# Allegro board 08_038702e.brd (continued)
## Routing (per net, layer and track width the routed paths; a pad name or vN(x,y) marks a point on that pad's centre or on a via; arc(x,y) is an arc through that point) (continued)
IO_L12_MRCC_12_JX3_P: length 74.2
  TOP w0.089: U1.AC13 v1(24.22,31.59)
  L7_SIG w0.089: v1(14.02,45.07) 12.63,45.07 12.24,45.45 12.24,46.06 12.9,46.72 13.89,46.72 14.35,46.26 14.84,46.26 15.4,45.7 16.18,45.7 16.56,46.08 16.56,51.16 16.18,51.54 12.37,51.54 11.99,51.92 11.99,53.83 11.61,54.21 10.85,54.21 10.47,54.59 10.47,57.47 11,58 16.42,58 16.44,58.02 19.97,58.02 20.5,57.49 20.5,55.99 20.88,55.61 24.94,55.61 25.33,55.23 25.33,50.78 24.94,50.4 20.88,50.4 20.5,50.02 20.5,46.46 20.88,46.08 22.26,46.08 23.84,44.5 23.84,31.96 v1(24.22,31.59)
  BOTTOM w0.089: JX3.86 13.29,44.97 13.64,45.32 13.77,45.32 v1(14.02,45.07)
IO_L12_MRCC_13_JX2_N: length 72.1
  TOP w0.089: U1.AC24 v1(24.22,19.59)
  L4_SIG w0.089: v1(45.52,8.49) 45.52,6.68 44.41,5.57 37.26,5.57 36.88,5.95 36.88,6.59 37.26,6.97 40.59,6.97 40.97,7.35 40.97,8.11 40.59,8.49 39.47,8.49 39.39,8.41 38.9,8.41 38.82,8.49 38.68,8.49 38.05,9.13 37.64,9.13 35.36,11.41 32.06,11.41 31.8,11.67 31.8,14.06 32.95,15.2 32.95,16.98 32.58,17.34 32.58,25.81 32.39,26 32.07,26 31.88,25.81 31.88,14.84 31.5,14.46 31.29,14.46 30.91,14.08 30.91,13.57 30.49,13.14 30.22,13.14 30.13,13.06 27.63,13.06 27.23,13.47 27.23,14.86 27.12,14.97 25.95,14.97 25.55,15.37 25.55,19.73 25.32,19.96 24.59,19.96 v1(24.22,19.59)
  BOTTOM w0.089: v1(45.52,8.49) 45.26,8.24 45.26,7.6 45.53,7.34 JX2.38
IO_L12_MRCC_13_JX2_P: length 72.1
  TOP w0.089: U1.AC23 v1(24.22,20.59)
  L4_SIG w0.089: v1(44.88,8.49) 45.04,8.49 45.26,8.27 45.26,7.94 45.14,7.81 45.14,7.6 45.26,7.47 45.26,6.79 44.3,5.82 37.37,5.82 37.14,6.06 37.14,6.48 37.37,6.71 40.69,6.71 41.22,7.24 41.22,8.21 40.69,8.74 39.36,8.74 39.28,8.66 39,8.66 38.92,8.74 38.79,8.74 38.15,9.38 37.75,9.38 35.46,11.67 32.16,11.67 32.06,11.77 32.06,13.95 33.2,15.09 33.2,17.08 32.83,17.45 32.83,25.92 32.5,26.25 31.96,26.25 31.63,25.92 31.63,14.95 31.39,14.71 31.19,14.71 30.66,14.18 30.66,13.68 30.38,13.4 30.11,13.4 30.03,13.32 27.74,13.32 27.48,13.57 27.48,14.97 27.23,15.22 26.06,15.22 25.81,15.48 25.81,19.83 25.42,20.22 24.47,20.22 24.39,20.3 24.39,20.42 v1(24.22,20.59)
  BOTTOM w0.089: v1(44.88,8.49) 45.05,8.33 45.05,7.6 44.73,7.28 JX2.36
IO_L12_MRCC_33_JX1_N: length 73.2
  TOP w0.089: U1.J3 v1(39.22,41.59)
  L4_SIG w0.089: v1(39.22,41.59) 39,41.38 38.79,41.38 38.67,41.25 37.51,41.25 37.44,41.18 37.15,41.18 36.88,41.45 36.88,45.07 37.26,45.45 45.39,45.45 45.77,45.83 45.77,46.8 45.39,47.18 43.54,47.18 43.23,47.49 43.23,47.93 43.46,48.16 44.24,48.16 44.32,48.24 47.78,48.24 48.95,49.41 48.95,51.42 49.33,51.8 60.91,51.8 61.14,51.57 61.14,51.27 60.91,51.04 49.75,51.04 49.46,50.74 49.46,50.32 49.75,50.02 61.88,50.02 63.62,51.76 63.62,52.76 63.62,52.76 63.81,52.94 63.96,52.94 64.02,53 64.02,53.13 63.83,53.32 63.68,53.32 63.62,53.39 63.62,53.64 v1(63.81,53.83)
  BOTTOM w0.089: JX1.83 63.93,54.59 63.68,54.34 63.68,53.96 v1(63.81,53.83)
IO_L12_MRCC_33_JX1_P: length 73.2
  TOP w0.089: U1.J4 v1(39.22,40.59)
  L4_SIG w0.089: v1(63.17,53.83) 63.36,53.64 63.36,51.86 61.77,50.27 49.86,50.27 49.71,50.42 49.71,50.63 49.86,50.78 61.01,50.78 61.39,51.16 61.39,51.67 61.01,52.05 49.22,52.05 48.69,51.52 48.69,49.51 47.68,48.5 44.22,48.5 44.13,48.41 43.36,48.41 42.98,48.04 42.98,47.39 43.44,46.93 45.29,46.93 45.52,46.69 45.52,45.93 45.29,45.7 37.15,45.7 36.62,45.17 36.62,41.34 37.04,40.93 37.55,40.93 37.61,40.99 38.81,40.99 v1(39.22,40.59)
  BOTTOM w0.089: JX1.81 63.13,54.67 63.43,54.38 63.43,54.08 v1(63.17,53.83)
IO_L12_MRCC_34_JX4_N: length 73.6
  TOP w0.089: U1.F7 v1(42.22,37.59)
  L4_SIG w0.089: v1(42.22,37.59) 41.84,37.22 41.84,36.69 41.87,36.46 42.08,36.25 43.35,36.25 43.55,36.45 43.55,36.76 43.97,37.18 47.43,37.18 48.47,38.22 49.29,38.22 49.39,38.31 51.78,38.31 52.01,38.08 52.88,38.08 54.03,39.22 55.04,39.22 55.15,39.33 55.64,39.33 55.7,39.27 57.72,39.27 57.76,39.22 60.5,39.22 61.14,38.59 64.08,38.59 64.46,38.97 67.18,38.97 67.45,38.7 67.78,38.7 67.93,38.84 76.76,38.84 77.27,39.35 91.22,39.35 91.62,38.95 91.62,36.87 91.75,36.74 91.75,33.66 91.22,33.13 84.51,33.13 84.46,33.08 84.24,33.08 83.27,32.11 v1(80.19,32.11)
  BOTTOM w0.089: v1(80.19,32.11) 80.44,32.37 80.57,32.37 80.77,32.17 JX4.48
IO_L12_MRCC_34_JX4_P: length 73.6
  TOP w0.089: U1.G7 v1(41.22,37.59)
  L4_SIG w0.089: v1(80.19,32.75) 80.19,32.59 80.41,32.37 83.16,32.37 84.14,33.34 84.36,33.34 84.4,33.38 91.11,33.38 91.49,33.76 91.49,36.63 91.37,36.76 91.37,38.84 91.11,39.1 77.37,39.1 76.87,38.59 68.03,38.59 67.89,38.44 67.35,38.44 67.07,38.72 64.57,38.72 64.19,38.34 61.03,38.34 60.4,38.97 57.18,38.97 57.13,39.01 55.59,39.01 55.53,39.08 55.25,39.08 55.15,38.97 54.13,38.97 52.99,37.83 51.82,37.83 51.53,37.54 49.62,37.54 49.2,37.96 48.57,37.96 47.54,36.92 44.08,36.92 43.81,36.65 43.81,36.34 43.46,36 41.97,36 41.62,36.34 41.59,36.68 41.59,37.22 v1(41.22,37.59)
  BOTTOM w0.089: v1(80.19,32.75) 80.32,32.62 80.44,32.62 80.79,32.97 JX4.46
IO_L12_MRCC_35_DATA_CLK_N: length 37.7
  TOP w0.089: U1.H14 v1(40.22,29.59) ; v6(61.2,31.29) U17.H11
  L14_SIG w0.089: v1(40.22,29.59) 39.91,29.59 39.82,29.5 39.82,29.41 40.04,29.19 40.46,29.19 40.57,29.3 40.57,30.86 40.43,31 35.89,31 35.61,31.27 35.61,31.96 35.89,32.24 47.78,32.24 47.92,32.38 53.15,32.38 53.77,33 54.61,33 55.17,32.44 57.24,32.44 58.2,31.48 60.01,31.48 60.12,31.59 60.46,31.59 60.46,31.59 60.52,31.59 60.82,31.29 60.82,31.21 61.05,30.97 61.05,30.97 61.16,30.86 61.29,30.86 61.39,30.97 61.39,31.07 61.37,31.1 v6(61.2,31.29)
IO_L12_MRCC_35_DATA_CLK_P: length 37.5
  TOP w0.089: U1.J14 v1(39.22,29.59) ; v6(61.2,30.49) U17.G11
  L14_SIG w0.089: v1(39.22,29.59) 39.22,29.62 39.3,29.7 39.44,29.7 39.57,29.57 39.57,29.3 39.93,28.94 40.57,28.94 40.82,29.19 40.82,30.97 40.54,31.25 35.99,31.25 35.87,31.38 35.87,31.86 35.99,31.99 47.89,31.99 48.03,32.12 53.26,32.12 53.88,32.75 54.5,32.75 55.06,32.18 57.13,32.18 58.09,31.22 60.05,31.22 60.27,31 60.67,31 61.17,30.49 v6(61.2,30.49)
IO_L13_35_TX_D0_N: length 33
  TOP w0.089: U1.D14 v1(44.22,29.59) ; v6(60.4,28.09) U17.E12
  L4_SIG w0.089: v6(60.4,28.09) 60.63,27.86 60.69,27.86 60.76,27.79 60.76,27.67 60.68,27.59 60.27,27.59 60.1,27.42 60.1,27.39 60.04,27.33 59.87,27.16 59.36,27.16 59.23,27.29 59.23,28.32 60.1,29.19 64.14,29.19 64.44,29.49 64.44,29.91 64.16,30.2 63.47,30.2 63.46,30.21 62.93,30.21 62.92,30.2 62.67,30.2 62.66,30.21 62.13,30.21 62.12,30.2 61.87,30.2 61.86,30.21 61.33,30.21 61.32,30.19 61.07,30.19 61.06,30.21 60.53,30.21 60.52,30.19 60.27,30.19 60.26,30.21 59.71,30.21 59.37,29.87 58.59,29.87 58.25,30.21 57.96,30.21 57.58,30.59 55.42,30.59 55.22,30.38 53.33,30.38 52.74,30.97 49.73,30.97 47.98,29.22 44.43,29.22 44.35,29.29 44.35,29.45 v1(44.22,29.59)
IO_L13_35_TX_D0_P: length 32.8
  TOP w0.089: v6(61.2,27.29) U17.D11 ; U1.D15 v1(44.22,28.59)
  L4_SIG w0.089: v1(44.22,28.59) 44.59,28.96 48.08,28.96 49.84,30.72 52.63,30.72 53.22,30.13 55.32,30.13 55.53,30.33 57.48,30.33 57.86,29.95 58.14,29.95 58.48,29.62 59.48,29.62 59.82,29.95 60.16,29.95 60.17,29.94 60.63,29.94 60.64,29.95 60.96,29.95 60.97,29.94 61.43,29.94 61.44,29.95 61.76,29.95 61.77,29.94 62.23,29.94 62.24,29.95 62.56,29.95 62.57,29.94 63.03,29.94 63.04,29.95 63.36,29.95 63.37,29.94 64.05,29.94 64.19,29.8 64.19,29.59 64.04,29.45 60,29.45 58.98,28.43 58.98,27.18 59.26,26.91 60.12,26.91 60.21,26.99 60.52,26.99 60.69,27.17 60.69,27.22 60.95,27.48 61.01,27.48 v6(61.2,27.29)
IO_L13_MRCC_12_JX3_N: length 74.1
  TOP w0.089: U1.AD14 v1(23.22,29.59)
  L15_SIG w0.089: v1(6.53,48.24) 6.28,47.99 3.86,47.99 3.48,47.61 3.48,40.47 3.25,40.24 2.82,40.24 2.59,40.47 2.59,51.95 2.82,52.18 7.29,52.18 8.05,51.42 12.65,51.42 12.76,51.3 14.4,51.3 14.93,51.83 14.93,53.22 15.17,53.45 20.01,53.45 20.25,53.22 20.25,50.38 19.74,49.87 19.74,38.84 19.86,38.72 19.86,38.56 19.95,38.47 19.95,38 21.02,36.92 21.35,36.92 21.55,36.73 21.55,36.39 22.02,35.92 22.35,35.92 22.55,35.73 22.55,35.39 23.02,34.92 23.35,34.92 23.55,34.73 23.55,34.39 24.02,33.93 24.35,33.93 24.55,33.73 24.55,31.45 24.35,31.25 24,31.25 23.59,30.84 23.59,29.86 23.84,29.61 23.84,29.32 23.7,29.19 23.29,29.19 23.22,29.27 v1(23.22,29.59)
  BOTTOM w0.089: v1(6.53,48.24) 6.85,47.92 6.97,47.92 7.22,48.17 JX3.93
IO_L13_MRCC_12_JX3_P: length 74.1
  TOP w0.089: U1.AC14 v1(24.22,29.59)
  L15_SIG w0.089: v1(6.53,47.48) 6.28,47.73 3.97,47.73 3.74,47.5 3.74,40.37 3.35,39.99 2.72,39.99 2.34,40.37 2.34,52.05 2.72,52.43 7.4,52.43 8.16,51.67 12.75,51.67 12.86,51.56 14.3,51.56 14.68,51.94 14.68,53.32 15.06,53.7 20.12,53.7 20.5,53.32 20.5,50.27 19.99,49.77 19.99,38.95 20.12,38.82 20.12,38.66 20.2,38.58 20.2,38.1 21.13,37.18 21.46,37.18 21.81,36.83 21.81,36.5 22.13,36.18 22.46,36.18 22.81,35.83 22.81,35.5 23.13,35.18 23.46,35.18 23.81,34.83 23.81,34.5 24.13,34.18 24.46,34.18 24.81,33.83 24.81,31.34 24.46,31 24.1,31 23.84,30.74 23.84,29.96 v1(24.22,29.59)
  BOTTOM w0.089: v1(6.53,47.48) 6.76,47.71 6.97,47.71 7.31,47.37 JX3.91
IO_L13_MRCC_13_JX2_N: length 73
  TOP w0.089: U1.AD21 v1(23.22,22.59)
  L4_SIG w0.089: v1(47.42,13.06) 48.81,11.67 57.08,11.67 57.46,11.28 57.46,10.65 57.08,10.27 54.55,10.27 54.47,10.35 54.19,10.35 54.11,10.27 48.42,10.27 48.19,10.04 48.19,5.32 47.8,4.93 45.14,4.93 44.76,4.55 44.76,4.05 44.38,3.66 36.25,3.66 35.87,4.05 35.87,9.78 34.87,10.78 32.67,10.78 31.91,10.01 30.3,10.01 29.9,10.42 29.9,11.31 29.28,11.92 25.69,11.92 25.45,12.16 25.45,14.35 25.35,14.46 25.09,14.46 24.69,14.86 24.69,15.62 24.58,15.73 24.03,15.73 23.62,16.13 23.62,22.92 23.61,22.94 23.57,22.94 v1(23.22,22.59)
  BOTTOM w0.089: v1(47.42,13.06) 47.42,12.61 47.64,12.39 47.64,12.05 47.93,11.76 JX2.43
IO_L13_MRCC_13_JX2_P: length 73.1
  TOP w0.089: U1.AD20 v1(23.22,23.59)
  L4_SIG w0.089: v1(23.22,23.59) 23.59,23.22 23.69,23.22 23.88,23.03 23.88,16.24 24.13,15.98 24.69,15.98 24.94,15.73 24.94,14.97 25.2,14.71 25.45,14.71 25.71,14.46 25.71,12.26 25.8,12.17 29.39,12.17 30.15,11.41 30.15,10.52 30.41,10.27 31.8,10.27 32.56,11.03 34.98,11.03 36.12,9.89 36.12,4.15 36.35,3.92 44.27,3.92 44.5,4.15 44.5,4.66 45.03,5.19 47.7,5.19 47.93,5.42 47.93,10.14 48.31,10.52 54,10.52 54.08,10.6 54.57,10.6 54.65,10.52 56.97,10.52 57.2,10.75 57.2,11.18 56.97,11.41 48.7,11.41 48.06,12.05 47.81,12.05 47.61,11.86 47.49,11.86 47.3,12.05 47.3,12.17 47.55,12.43 47.55,12.56 47.43,12.68 v1(47.04,12.68)
  BOTTOM w0.089: JX2.41 47.13,11.75 47.42,12.05 47.42,12.3 v1(47.04,12.68)
IO_L13_MRCC_33_JX1_N: length 73.8
  TOP w0.089: U1.M5 v1(36.22,39.59)
  L4_SIG w0.089: v1(63.74,49.64) 63.87,49.51 64.31,49.51 64.44,49.64 64.44,49.89 64.31,50.02 63.81,50.02 63.63,50.19 63.62,50.19 63.62,50.49 64.04,50.91 77.92,50.91 78.16,50.68 78.16,45.93 77.92,45.7 73.35,45.7 72.82,45.17 72.82,44.9 72.59,44.67 60.78,44.67 60.53,44.92 60.53,45.37 60.28,45.63 58.08,45.63 57.84,45.87 57.84,46.06 57.31,46.59 49.22,46.59 48.82,46.19 48.82,44.54 47.54,43.25 39.92,43.25 39.55,42.89 39.55,40.45 39.35,40.25 38.8,40.25 38.55,40.01 38.55,39.45 38.32,39.22 36.59,39.22 v1(36.22,39.59)
  BOTTOM w0.089: v1(63.74,49.64) 63.68,49.7 63.68,50.02 63.93,50.27 JX1.84
IO_L13_MRCC_33_JX1_P: length 73.8
  TOP w0.089: U1.M6 v1(36.22,38.59)
  L4_SIG w0.089: v1(63.23,49.64) 63.36,49.77 63.36,50.59 63.93,51.16 78.03,51.16 78.41,50.78 78.41,45.83 78.03,45.45 73.46,45.45 73.08,45.07 73.08,44.79 72.7,44.41 60.68,44.41 60.28,44.81 60.28,45.27 60.17,45.37 57.97,45.37 57.58,45.76 57.58,45.96 57.2,46.34 49.33,46.34 49.07,46.08 49.07,44.43 47.64,43 40.02,43 39.81,42.78 39.81,40.34 39.46,40 38.9,40 38.81,39.9 38.81,39.34 38.42,38.96 36.59,38.96 v1(36.22,38.59)
  BOTTOM w0.089: JX1.82 63.13,50.29 63.46,49.96 63.46,49.87 v1(63.23,49.64)
IO_L13_MRCC_34_JX4_N: length 73.3
  TOP w0.089: U1.C7 v1(45.22,37.59)
  L17_SIG w0.089: v1(45.22,37.59) 44.82,37.19 44.14,37.19 43.87,37.46 43.87,37.91 43.96,38 47.29,38 47.29,38 48.55,38 48.84,37.7 49.39,37.7 49.55,37.54 53.68,37.54 54.67,36.55 56.44,36.55 56.5,36.61 57.13,36.61 57.32,36.43 58.35,36.43 58.89,36.98 60.19,36.98 60.24,37.02 60.52,37.02 60.6,36.94 71.34,36.94 71.88,36.4 71.88,36.19 71.92,36.15 71.92,33.81 72.3,33.43 72.51,33.43 72.51,33.43 73.14,33.43 76.14,30.43 77.16,30.43 77.4,30.2 77.4,20.32 79.07,18.65 82.22,18.65 82.6,19.03 82.6,24.72 82.49,24.83 82.49,25.11 82.6,25.22 82.6,29.98 82.83,30.21 83.19,30.21 83.36,30.03 83.36,29.7 83.49,29.57 83.62,29.57 83.75,29.7 83.75,30.08 83.87,30.21 84.13,30.21 v1(84.38,29.95)
  BOTTOM w0.089: v1(84.38,29.95) 84.55,30.12 84.89,30.12 85.24,29.77 JX4.53
IO_L13_MRCC_34_JX4_P: length 73.3
  TOP w0.089: U1.C8 v1(45.22,36.59)
  L17_SIG w0.089: v1(45.22,36.59) 44.87,36.94 44.03,36.94 43.61,37.36 43.61,38.01 43.85,38.25 47.39,38.25 47.39,38.25 48.65,38.25 48.95,37.95 49.39,37.95 49.65,38.22 51.53,38.22 51.93,37.81 53.76,37.81 54.72,36.86 54.77,36.81 56.33,36.81 56.39,36.87 57.24,36.87 57.42,36.68 58.22,36.68 58.71,37.18 58.74,37.18 58.79,37.23 60.09,37.23 60.13,37.27 60.62,37.27 60.7,37.19 71.45,37.19 72.13,36.51 72.13,36.29 72.17,36.25 72.17,33.91 72.4,33.68 73.25,33.68 76.24,30.69 77.27,30.69 77.65,30.3 77.65,20.43 79.17,18.9 82.12,18.9 82.35,19.14 82.35,24.62 82.24,24.73 82.24,25.22 82.35,25.33 82.35,30.08 82.73,30.46 84.25,30.46 v1(84.38,30.59)
  BOTTOM w0.089: v1(84.38,30.59) 84.63,30.33 84.89,30.33 85.13,30.57 JX4.51
IO_L14_35_TX_D1_N: length 32.1
  TOP w0.089: v6(61.2,28.09) U17.E11 ; U1.E15 v1(43.22,28.59)
  L4_SIG w0.089: v1(43.22,28.59) 43.11,28.59 43,28.48 43,28.35 43.11,28.25 48.13,28.25 49.71,29.83 51.85,29.83 52.88,28.79 52.88,27.01 53.12,26.78 53.29,26.78 53.52,27.01 53.52,28.5 54.05,29.03 54.93,29.03 55.12,28.84 56.47,28.84 56.51,28.88 57.21,28.88 57.71,28.38 57.71,27.84 57.96,27.58 57.96,26.78 58.55,26.19 58.82,26.19 59.03,26.2 59.73,25.5 59.87,25.5 59.98,25.38 61,25.38 61.01,25.39 62.32,25.39 62.5,25.58 62.5,25.96 62.32,26.14 61.67,26.14 61.56,26.26 61.56,27.32 61.77,27.54 61.77,27.79 61.52,28.05 61.24,28.05 v6(61.2,28.09)
IO_L14_35_TX_D1_P: length 32.4
  TOP w0.089: U1.F15 v1(42.22,28.59) ; v6(62,27.29) U17.D10
  L4_SIG w0.089: v6(62,27.29) 62,27.29 62.38,26.91 62.69,26.91 62.8,26.79 62.92,26.79 63.09,26.62 63.09,26.5 63.3,26.3 63.3,25.51 62.92,25.13 59.88,25.13 59.76,25.24 59.63,25.24 58.93,25.94 58.44,25.94 57.71,26.67 57.71,27.48 57.46,27.73 57.46,28.28 57.11,28.63 56.83,28.63 56.79,28.59 55.01,28.59 54.82,28.78 54.15,28.78 53.77,28.4 53.77,26.91 53.39,26.52 53.01,26.52 52.63,26.91 52.63,28.68 51.74,29.57 49.81,29.57 48.24,28 42.79,28 42.72,28.07 42.72,28.09 v1(42.22,28.59)
IO_L14_SRCC_12_JX3_N: length 72
  TOP w0.089: U1.AB14 v1(25.22,29.59)
  L4_SIG w0.089: v1(15.17,48.75) 15.04,48.62 13.13,48.62 12.5,49.26 12.5,55.88 12.73,56.12 13.19,56.12 13.4,55.91 13.89,55.91 14.1,56.12 18.45,56.12 18.98,56.65 18.98,57.53 19.21,57.77 20.27,57.77 20.5,57.53 20.5,55.5 21.03,54.97 24.97,54.97 25.2,54.74 25.2,51.01 24.97,50.78 17.96,50.78 17.58,50.4 17.58,48.75 17.96,48.37 20.12,48.37 20.5,47.99 20.5,45.29 21.23,44.56 21.41,44.56 21.64,44.33 21.64,43.85 21.62,43.83 21.62,37.34 21.64,37.33 21.64,36.85 21.62,36.83 21.62,34.34 21.97,34 22.28,34 22.62,33.66 22.62,33.34 22.97,33 23.28,33 23.62,32.66 23.62,32.34 23.97,32 24.28,32 24.62,31.66 24.62,31.34 24.97,31 25.49,31 25.62,30.86 25.62,30.34 25.97,30 26.28,30 26.55,29.73 26.55,29.45 26.35,29.25 26.04,29.25 26.01,29.22 25.48,29.22 25.48,29.22 25.33,29.06 24.82,29.06 24.69,29.19 24.69,29.7 24.83,29.84 24.96,29.84 v1(25.22,29.59)
  BOTTOM w0.089: JX3.94 13.42,48.17 13.64,47.95 13.84,47.95 14.47,48.58 15,48.58 v1(15.17,48.75)
IO_L14_SRCC_12_JX3_P: length 72
  TOP w0.089: U1.AB15 v1(25.22,28.59)
  L4_SIG w0.089: v1(25.22,28.59) 25.59,28.96 26.11,28.96 26.46,29 26.81,29.34 26.81,29.83 26.39,30.25 26.07,30.25 25.88,30.45 25.88,30.97 25.6,31.25 25.08,31.25 24.88,31.45 24.88,31.76 24.39,32.25 24.08,32.25 23.88,32.45 23.88,32.76 23.39,33.25 23.08,33.25 22.88,33.45 22.88,33.76 22.39,34.25 22.08,34.25 21.88,34.45 21.88,36.73 21.9,36.75 21.9,37.43 21.88,37.45 21.88,43.73 21.9,43.75 21.9,44.43 21.52,44.81 21.33,44.81 20.75,45.39 20.75,48.09 20.22,48.62 18.06,48.62 17.83,48.85 17.83,50.3 18.06,50.53 25.07,50.53 25.45,50.91 25.45,54.85 25.07,55.23 21.13,55.23 20.75,55.61 20.75,57.64 20.37,58.02 19.1,58.02 18.72,57.64 18.72,56.75 18.34,56.37 13.99,56.37 13.78,56.16 13.5,56.16 13.29,56.37 12.63,56.37 12.24,55.99 12.24,49.15 13.03,48.37 15.04,48.37 v1(15.17,48.24)
  BOTTOM w0.089: v1(15.17,48.24) 15.04,48.37 14.56,48.37 13.93,47.73 13.64,47.73 13.28,47.37 JX3.92
IO_L14_SRCC_13_JX2_N: length 72
  TOP w0.089: U1.AC22 v1(24.22,21.59)
  L6_SIG w0.089: v1(24.22,21.59) 24.59,21.96 25.32,21.96 25.62,21.66 25.62,17.34 25.97,17 26.18,17 26.55,16.63 26.55,16.56 28.01,15.09 33.47,15.09 34.98,13.59 34.98,12.83 36.19,11.61 36.43,11.61 36.48,11.56 36.97,11.56 37.03,11.61 46.24,11.61 46.62,11.99 46.62,12.79 47.66,13.82 48.04,13.82 48.42,14.21 52.12,14.21 52.38,13.95 53.79,13.95 54.54,13.21 54.54,10.93 55.06,10.4 55.7,10.4 55.93,10.16 55.93,7.8 56.33,7.39 57.19,7.39 57.48,7.11 57.48,6.71 57.22,6.46 56.46,6.46 55.93,5.93 55.93,5.88 55.7,5.65 44.48,5.65 44.25,5.88 44.25,7.12 44.48,7.35 46.89,7.35 47.16,7.61 47.3,7.75 47.3,7.98 47.42,8.11 47.93,8.11 48.06,8.24 48.06,8.74 47.93,8.87 47.8,8.87 v1(47.55,8.62)
  BOTTOM w0.089: JX2.44 47.93,7.31 47.64,7.6 47.64,8.07 47.45,8.26 47.45,8.52 v1(47.55,8.62)
IO_L14_SRCC_13_JX2_P: length 72
  TOP w0.089: U1.AC21 v1(24.22,22.59)
  L6_SIG w0.089: v1(24.22,22.59) 24.59,22.22 25.42,22.22 25.88,21.76 25.88,17.45 26.08,17.25 26.29,17.25 26.8,16.74 26.8,16.66 28.12,15.35 33.58,15.35 35.23,13.7 35.23,12.94 36.3,11.87 36.53,11.87 36.59,11.81 36.87,11.81 36.92,11.87 46.13,11.87 46.36,12.1 46.36,12.89 47.55,14.08 47.93,14.08 48.31,14.46 48.52,14.46 48.52,14.46 52.23,14.46 52.48,14.21 53.9,14.21 54.79,13.32 54.79,11.03 55.17,10.65 55.81,10.65 56.19,10.27 56.19,7.9 56.44,7.65 57.3,7.65 57.73,7.21 57.73,6.35 57.58,6.2 56.57,6.2 56.19,5.82 56.19,5.78 55.81,5.4 44.38,5.4 43.99,5.78 43.99,7.22 44.38,7.6 46.79,7.6 46.98,7.79 47.04,7.86 v1(47.04,8.62)
  BOTTOM w0.089: JX2.42 47.13,7.31 47.42,7.6 47.42,7.98 47.23,8.17 47.23,8.43 v1(47.04,8.62)
IO_L14_SRCC_33_JX1_N: length 74.4
  TOP w0.089: U1.L4 v1(37.22,40.59)
  L14_SIG w0.089: v1(50.34,49.64) 50.09,49.89 50.09,50.27 49.84,50.53 49.07,50.53 48.69,50.15 48.69,49.64 47.55,48.5 47.55,47.26 47.53,47.24 47.53,44.63 47.46,44.56 44.98,44.56 44.9,44.48 42.13,44.48 41.62,43.97 41.62,40.52 41.32,40.22 40.21,40.22 40.17,40.18 39.97,40.18 39.62,39.83 39.62,38.45 39.35,38.18 37.89,38.18 37.63,37.91 37.63,36.39 37.41,36.18 34.97,36.18 34.63,35.83 34.63,35.8 34.07,35.25 19.62,35.25 18.98,35.9 18.98,36.54 18.85,36.66 18.85,37.6 18.95,37.7 19.86,37.7 21.64,35.92 22.07,35.92 22.08,35.92 34.09,35.92 34.88,36.71 34.88,36.73 35.08,36.92 35.09,36.92 35.1,36.94 36.48,36.94 36.63,37.09 36.63,37.09 36.88,37.34 36.88,38.73 37.12,38.97 38.35,38.97 38.38,39 38.46,39 38.81,39.34 38.81,39.83 38.46,40.18 38.42,40.18 38.38,40.22 37.59,40.22 v1(37.22,40.59)
  BOTTOM w0.089: v1(50.34,49.64) 50.22,49.64 49.99,49.87 49.99,50.05 50.33,50.38 JX1.50
IO_L14_SRCC_33_JX1_P: length 74.4
  TOP w0.089: U1.L5 v1(37.22,39.59)
  L14_SIG w0.089: v1(37.22,39.59) 37.01,39.79 37.01,39.99 37.11,40.08 37.36,40.08 37.48,39.96 38.28,39.96 38.32,39.92 38.35,39.92 38.55,39.73 38.55,39.45 38.35,39.25 38.27,39.25 38.24,39.22 37.02,39.22 36.63,38.83 36.63,37.45 36.37,37.2 36.37,37.19 34.98,37.19 33.97,36.18 21.97,36.18 21.97,36.18 21.75,36.18 19.97,37.95 18.85,37.95 18.59,37.7 18.59,36.56 18.72,36.43 18.72,35.8 19.52,35 34.18,35 34.88,35.7 34.88,35.73 35.08,35.92 37.52,35.92 37.88,36.28 37.88,37.81 38,37.92 39.46,37.92 39.88,38.34 39.88,39.73 40.08,39.92 40.28,39.92 40.31,39.96 41.42,39.96 41.88,40.42 41.88,43.86 42.24,44.22 45,44.22 45.08,44.3 47.57,44.3 47.79,44.52 47.79,47.14 47.8,47.16 47.8,48.39 48.95,49.53 48.95,50.04 49.18,50.27 49.73,50.27 49.84,50.17 49.84,49.89 v1(49.58,49.64)
  BOTTOM w0.089: JX1.48 49.53,50.2 49.77,49.96 49.77,49.83 v1(49.58,49.64)
IO_L14_SRCC_34_JX4_N: length 72.1
  TOP w0.089: U1.C6 v1(45.22,38.59)
  L6_SIG w0.089: v1(45.22,38.59) 45.21,38.59 44.88,38.59 44.8,38.68 44.8,38.81 44.96,38.97 49.61,38.97 49.65,39.01 51.53,39.01 51.58,38.97 55.15,38.97 55.25,39.08 55.53,39.08 55.64,38.97 56.01,38.97 56.05,39.01 56.33,39.01 56.38,38.97 56.81,38.97 56.85,39.01 57.13,39.01 57.18,38.97 60.38,38.97 60.89,38.46 62.92,38.46 63.17,38.72 66.35,38.72 67.12,37.94 69.05,37.94 69.42,37.57 77.71,37.57 79.49,35.8 79.58,35.8 79.7,35.67 81.99,35.67 82.09,35.56 82.09,23.58 81.86,23.35 81.31,23.35 81.08,23.58 81.08,33.11 80.68,33.51 78.94,33.51 78.41,32.98 78.41,30.97 79.36,30.02 79.67,30.02 79.86,29.83 v1(80.19,29.83)
  BOTTOM w0.089: v1(80.19,29.83) 80.44,30.08 80.57,30.08 80.88,29.77 JX4.54
IO_L14_SRCC_34_JX4_P: length 72.1
  TOP w0.089: U1.D6 v1(44.22,38.59)
  L6_SIG w0.089: v1(80.19,30.46) 79.86,30.46 79.67,30.27 79.47,30.27 78.67,31.07 78.67,32.87 79.05,33.26 80.57,33.26 80.82,33 80.82,23.48 81.21,23.1 81.97,23.1 82.35,23.48 82.35,35.67 82.09,35.92 79.81,35.92 79.68,36.05 79.59,36.05 77.81,37.83 69.52,37.83 69.15,38.2 67.22,38.2 66.45,38.97 63.07,38.97 62.81,38.72 60.99,38.72 60.48,39.22 57.28,39.22 57.24,39.27 55.7,39.27 55.64,39.33 55.15,39.33 55.04,39.22 51.68,39.22 51.64,39.27 49.55,39.27 49.5,39.22 44.85,39.22 44.62,38.99 v1(44.22,38.59)
  BOTTOM w0.089: JX4.52 80.81,30.57 80.57,30.33 80.32,30.33 v1(80.19,30.46)
IO_L15_12_JX3_N: length 72.8
  TOP w0.089: U1.AD15 v1(23.22,28.59)
  L4_SIG w0.089: v1(23.22,28.59) 22.84,28.22 22.34,28.22 22.3,28.18 21.97,28.18 21.62,27.83 21.62,27.5 21.3,27.18 20.97,27.18 20.62,26.83 20.62,26.5 20.5,26.38 20.5,12.79 20.27,12.55 19.21,12.55 18.57,13.19 16.16,13.19 15.93,13.42 15.93,13.85 16.16,14.08 17.29,14.08 17.43,13.93 17.98,13.93 18.12,14.08 18.45,14.08 18.98,14.61 18.98,15.45 18.45,15.98 17.81,15.98 17.58,16.22 17.58,18.76 17.05,19.29 16.71,19.29 16.48,19.52 16.48,27.71 16.61,27.84 16.61,28.33 16.48,28.46 16.48,31.69 15.55,32.62 15.55,35.41 15.29,35.67 14.53,35.67 13.51,36.68 13.51,46.11 9.36,50.27 6.78,50.27 v1(6.53,50.53)
  BOTTOM w0.089: JX3.99 7.37,50.57 7.04,50.24 6.82,50.24 v1(6.53,50.53)
IO_L15_12_JX3_P: length 72.8
  TOP w0.089: U1.AD16 v1(23.22,27.59)
  L4_SIG w0.089: v1(6.53,49.77) 6.78,50.02 9.25,50.02 13.26,46.01 13.26,36.58 14.42,35.41 15.19,35.41 15.29,35.31 15.29,32.52 16.23,31.58 16.23,28.35 16.35,28.23 16.35,27.95 16.23,27.82 16.23,19.41 16.61,19.03 16.94,19.03 17.32,18.65 17.32,16.11 17.71,15.73 18.34,15.73 18.72,15.35 18.72,14.71 18.34,14.33 18.02,14.33 17.87,14.19 17.54,14.19 17.39,14.33 16.05,14.33 15.67,13.95 15.67,13.32 16.05,12.94 18.47,12.94 19.1,12.3 20.37,12.3 20.75,12.68 20.75,26.27 20.88,26.4 20.88,26.73 21.08,26.93 21.41,26.93 21.88,27.4 21.88,27.73 22.08,27.93 22.41,27.93 22.44,27.96 22.84,27.96 v1(23.22,27.59)
  BOTTOM w0.089: JX3.97 7.29,49.77 7.04,50.02 6.78,50.02 v1(6.53,49.77)
IO_L15_13_JX2_N: length 72.5
  TOP w0.089: U1.AF20 v1(21.22,23.59)
  L6_SIG w0.089: v3(50.34,12.94) 50.09,12.68 50.09,10.61 49.5,10.01 45.82,10.01 45.69,10.14 42.94,10.14 42.81,10.01 39.07,10.01 38.79,9.73 38.79,7.71 39.17,7.33 39.17,3.41 38.53,2.78 35.87,2.78 35.1,2.01 32.56,2.01 32.18,2.39 32.18,4.05 32.56,4.43 34.74,4.43 34.98,4.66 34.98,5.21 34.74,5.44 33.33,5.44 32.95,5.82 32.95,7.35 33.33,7.73 35.89,7.73 36.12,7.96 36.12,9.78 35.89,10.01 29.9,10.01 29.14,10.78 29.14,11.49 28.75,11.88 27.66,11.88 26.98,12.55 26.98,12.68 26.6,13.06 25.83,13.06 25.45,13.44 25.45,13.82 25.07,14.21 23.42,14.21 22.58,15.05 22.58,23.4 22.62,23.45 22.62,23.84 22.51,23.96 21.59,23.96 v1(21.22,23.59)
  L19_GND w0.089: v4(50.22,12.43) 50.22,12.81 v3(50.34,12.94)
  BOTTOM w0.089: JX2.49 50.33,11.77 50.05,12.05 50.05,12.26 v4(50.22,12.43)
IO_L15_13_JX2_P: length 72.5
  TOP w0.089: U1.AF19 v1(21.22,24.59)
  L6_SIG w0.089: v3(49.58,12.94) 49.84,12.68 49.84,10.71 49.39,10.27 45.92,10.27 45.79,10.4 42.83,10.4 42.7,10.27 38.97,10.27 38.54,9.84 38.54,7.6 38.91,7.22 38.91,3.52 38.43,3.03 35.76,3.03 35,2.27 32.67,2.27 32.44,2.5 32.44,3.94 32.67,4.17 34.85,4.17 35.23,4.55 35.23,5.32 34.85,5.7 33.43,5.7 33.2,5.93 33.2,7.24 33.43,7.47 35.99,7.47 36.37,7.86 36.37,9.89 35.99,10.27 30.02,10.27 29.39,10.9 29.39,11.59 28.85,12.13 27.76,12.13 27.23,12.66 27.23,12.79 26.7,13.32 25.94,13.32 25.71,13.55 25.71,13.93 25.18,14.46 23.53,14.46 22.83,15.16 22.83,23.29 22.88,23.34 22.88,23.95 22.61,24.22 21.48,24.22 21.38,24.12 21.16,24.11 21.08,24.19 21.08,24.34 v1(21.22,24.59)
  L19_GND w0.089: v4(49.71,12.43) 49.71,12.81 v3(49.58,12.94)
  BOTTOM w0.089: JX2.47 49.53,11.74 49.84,12.05 49.84,12.3 v4(49.71,12.43)
IO_L15_33_JX1_N: length 72.6
  TOP w0.089: U1.N2 v1(35.22,42.59)
  L15_SIG w0.089: v1(35.22,42.59) 35.59,42.22 35.68,42.22 35.71,42.25 36.35,42.25 36.62,42.52 36.62,49.61 37.67,50.65 38.51,50.65 39.04,50.12 39.04,48.77 38.79,48.52 38.79,44.96 38.2,44.38 37.9,44.07 37.9,43.75 37.88,43.73 37.88,43.45 37.9,43.43 37.9,42.75 37.88,42.73 37.88,42.45 37.9,42.43 37.9,41.75 37.88,41.73 37.88,41.45 37.9,41.43 37.9,40.75 37.88,40.73 37.88,40.45 37.9,40.43 37.9,39.75 37.88,39.73 37.88,37.42 38.11,37.19 38.55,37.19 38.62,37.26 38.62,43.83 39.1,44.3 39.95,44.3 40.18,44.54 40.18,48.65 40.59,49.05 41.6,49.05 41.71,49.15 41.71,51.39 42.11,51.8 52.78,51.8 53.01,52.03 53.01,55.5 52.78,55.73 49.1,55.73 48.57,56.26 48.57,58.4 48.95,58.78 52,58.78 52.5,58.27 52.5,57.51 v1(52.63,57.39)
  BOTTOM w0.089: JX1.55 52.73,56.15 52.38,56.5 52.38,57.13 v1(52.63,57.39)
IO_L15_33_JX1_P: length 72.6
  TOP w0.089: U1.N3 v1(35.22,41.59)
  L15_SIG w0.089: v1(51.87,57.39) 52.12,57.39 52.25,57.51 52.25,57.64 52.17,57.72 52.15,57.72 52.07,57.79 52.07,57.84 52.25,58.02 52.25,58.17 51.89,58.53 49.05,58.53 48.82,58.3 48.82,56.37 49.2,55.99 52.88,55.99 53.27,55.61 53.27,51.92 52.88,51.54 42.22,51.54 41.96,51.29 41.96,49.05 41.71,48.8 40.69,48.8 40.44,48.54 40.44,44.43 40.06,44.05 39.2,44.05 38.88,43.73 38.88,37.16 38.66,36.94 38.01,36.94 37.62,37.32 37.62,39.83 37.64,39.85 37.64,40.32 37.62,40.34 37.62,40.83 37.64,40.85 37.64,41.32 37.62,41.34 37.62,41.83 37.64,41.85 37.64,42.32 37.62,42.34 37.62,42.83 37.64,42.85 37.64,43.32 37.62,43.34 37.62,43.83 37.64,43.85 37.64,44.18 38.1,44.63 38.53,45.07 38.53,48.62 38.79,48.88 38.79,50.02 38.41,50.4 37.77,50.4 36.88,49.51 36.88,42.42 36.46,42 35.82,42 35.78,41.96 35.59,41.96 v1(35.22,41.59)
  BOTTOM w0.089: v1(51.87,57.39) 52.16,57.09 52.16,56.41 51.93,56.17 JX1.53
IO_L15_34_JX4_N: length 74
  TOP w0.089: U1.B9 v1(46.22,35.59)
  L18_SIG w0.089: v1(84.25,28.05) 84.13,28.18 84,28.18 83.94,28.11 83.81,28.11 83.75,28.18 83.62,28.18 83.43,27.98 83.3,27.98 83.11,28.18 82.73,28.18 82.6,28.3 82.6,28.45 80.95,30.1 80.95,30.21 77.52,33.64 77.52,36.68 74.86,39.35 74.86,40.77 71.7,43.92 68.76,43.92 63.68,49 63.04,49 63,49.05 62.99,49.05 62.64,49.39 62.64,49.4 60.38,51.67 46.26,51.67 43.23,48.64 43.23,47.12 42.22,46.1 42.22,45.16 42.13,45.08 42.13,44.8 42.22,44.72 42.22,44.41 42.37,44.25 42.39,44.25 42.81,43.83 42.81,39.03 42.82,38.98 42.88,38.92 42.88,38.45 43.08,38.25 43.46,38.25 43.88,37.83 43.88,37.45 44.08,37.25 44.33,37.25 44.4,37.18 45.46,37.18 45.81,36.83 45.81,36.83 45.84,36.79 45.84,35.96 v1(46.22,35.59)
  BOTTOM w0.089: JX4.59 85.18,27.37 84.63,27.92 84.63,27.99 84.57,28.05 v1(84.25,28.05)
IO_L15_34_JX4_P: length 74
  TOP w0.089: U1.C9 v1(45.22,35.59)
  L18_SIG w0.089: v1(84.25,28.56) 84.13,28.43 82.98,28.43 81.21,30.21 81.21,30.31 77.78,33.74 77.78,36.79 75.11,39.46 75.11,40.88 71.81,44.18 68.86,44.18 63.78,49.26 63.15,49.26 63.1,49.3 63.1,49.3 62.9,49.5 62.9,49.51 60.48,51.92 46.15,51.92 42.98,48.75 42.98,47.23 41.96,46.21 41.96,45.27 41.88,45.18 41.88,44.69 41.96,44.61 41.96,44.3 42.27,44 42.28,44 42.55,43.73 42.55,38.99 42.57,38.93 42.59,38.85 42.62,38.82 42.62,38.34 42.97,38 43.35,38 43.62,37.73 43.62,37.34 43.97,37 44.22,37 44.3,36.92 45.35,36.92 45.55,36.73 45.55,36.72 45.59,36.68 45.59,35.96 v1(45.22,35.59)
  BOTTOM w0.089: JX4.57 84.98,28.17 84.93,28.12 84.81,28.12 84.66,28.26 84.55,28.26 v1(84.25,28.56)
IO_L15_35_TX_D2_N: length 31.6
  TOP w0.089: U1.C16 v1(45.22,27.59) ; v6(62,28.09) U17.E10
  L6_SIG w0.089: 60.38,27.67 61.59,27.67 61.69,27.77 61.69,27.79 v6(62,28.09) ; 60.38,27.67 60.3,27.59 60.27,27.59 ; 60.38,27.67 60.35,27.67 60.27,27.59 ; 60.27,27.59 60.1,27.42 60.1,27.2 60.06,27.16 59.87,27.16 59.36,27.67 58.98,27.67 58.73,27.41 58.73,26.78 59.84,25.66 59.84,25.21 59.02,24.38 57.69,24.38 57.58,24.49 57.58,25.4 57.69,25.51 57.94,25.51 58.35,25.91 58.35,26.27 57.2,27.41 56.57,27.41 56.4,27.24 54.09,27.24 53.69,26.84 53.69,25.25 53.56,25.13 53.01,25.13 52.88,25.25 52.88,26.91 52.55,27.24 50.45,27.24 50.41,27.29 49.58,27.29 49.2,26.91 48.69,26.91 48.38,27.22 45.48,27.22 45.41,27.14 45.28,27.01 45.16,27.01 45.01,27.16 45.01,27.38 v1(45.22,27.59)
IO_L15_35_TX_D2_P: length 31.5
  TOP w0.089: v6(62.8,27.29) U17.D9 ; U1.C17 v1(45.22,26.59)
  L6_SIG w0.089: v6(62.8,27.29) 62.42,27.67 62.03,27.67 61.95,27.59 61.87,27.59 61.49,27.2 61.49,27.16 61.32,26.99 60.25,26.99 60.16,26.91 59.76,26.91 59.26,27.41 59.09,27.41 58.98,27.31 58.98,26.88 60.1,25.77 60.1,25.1 59.12,24.13 57.58,24.13 57.33,24.38 57.33,25.51 57.58,25.76 57.84,25.76 58.09,26.02 58.09,26.17 57.1,27.16 56.67,27.16 56.5,26.99 54.2,26.99 53.95,26.73 53.95,25.15 53.67,24.87 52.91,24.87 52.63,25.15 52.63,26.8 52.44,26.99 50.35,26.99 50.3,27.03 49.69,27.03 49.31,26.65 48.59,26.65 48.28,26.96 45.59,26.96 v1(45.22,26.59)
IO_L16_12_JX3_N: length 72
  TOP w0.089: U1.AF14 v1(21.22,29.59)
  L4_SIG w0.089: v1(14.66,51.04) 14.91,51.04 15.29,50.65 15.4,50.65 15.8,50.25 15.93,50.25 16.56,49.62 16.56,48.03 16.79,47.8 19.61,47.8 19.99,47.42 19.99,46.46 19.61,46.08 16.67,46.08 16.44,45.85 16.44,45.57 16.82,45.19 17.74,45.19 18.34,44.59 18.34,43.95 17.94,43.54 16.29,43.54 16.05,43.31 16.05,42.76 16.29,42.53 17.96,42.53 18.34,42.15 18.34,41.11 18.38,41.06 18.38,40.74 18.85,40.27 18.85,35.69 18.32,35.16 17.81,35.16 17.58,34.93 17.58,20.03 17.81,19.79 18.23,19.79 18.47,20.03 18.47,34.65 18.85,35.03 19.86,35.03 20.25,34.65 20.25,29.57 20.6,29.22 20.84,29.22 v1(21.22,29.59)
  BOTTOM w0.089: JX3.100 13.22,50.57 13.51,50.27 13.72,50.27 14.22,50.78 14.4,50.78 v1(14.66,51.04)
IO_L16_12_JX3_P: length 72
  TOP w0.089: U1.AF15 v1(21.22,28.59)
  L4_SIG w0.089: v1(21.22,28.59) 20.84,28.96 20.49,28.96 19.99,29.46 19.99,34.55 19.76,34.78 18.95,34.78 18.72,34.55 18.72,19.92 18.34,19.54 17.71,19.54 17.32,19.92 17.32,35.03 17.71,35.41 18.21,35.41 18.59,35.8 18.59,40.17 18.13,40.63 18.13,40.96 18.09,41 18.09,42.04 17.85,42.27 16.18,42.27 15.8,42.65 15.8,43.42 16.18,43.8 17.83,43.8 18.09,44.05 18.09,44.49 17.63,44.94 16.71,44.94 16.18,45.47 16.18,45.96 16.56,46.34 19.5,46.34 19.74,46.57 19.74,47.31 19.5,47.54 16.69,47.54 16.31,47.92 16.31,49.51 15.82,50 15.69,50 15.29,50.4 15.17,50.4 15.17,50.42 14.93,50.65 14.87,50.65 14.78,50.57 14.78,50.53 v1(14.66,50.4)
  BOTTOM w0.089: v1(14.66,50.4) 14.57,50.4 14.4,50.57 14.31,50.57 13.77,50.02 13.51,50.02 13.27,49.77 JX3.98
IO_L16_13_JX2_N: length 72.5
  TOP w0.089: U1.AE21 v1(22.22,22.59)
  L4_SIG w0.089: v3(50.34,8.49) 50.22,8.36 v4(50.22,7.98) 50.53,7.67 50.53,7.54 50.22,7.22 50.22,6.99 49.56,6.33 49.46,6.33 49.07,5.95 49.07,4.17 49.18,4.06 49.18,3.97 49.38,3.77 49.66,3.77 49.68,3.79 52.63,3.79 53.01,3.41 53.01,2.87 52.54,2.39 48.31,2.39 47.8,2.9 35.2,2.9 34.99,3.11 34.71,3.11 34.5,2.9 33.61,2.9 33.2,3.31 33.2,3.89 33.61,4.3 34.6,4.3 35.1,4.81 35.1,5.7 34.85,5.95 34.22,5.95 33.96,6.2 33.96,6.71 34.22,6.97 34.85,6.97 35.1,7.22 35.1,7.62 34.87,7.86 34.24,7.86 33.73,8.36 33.45,8.36 33.2,8.11 33.2,5.44 32.95,5.19 32.31,5.19 32.06,5.44 32.06,6.31 32.18,6.44 32.18,8.89 32.08,9 31.06,9 30.81,9.25 29.9,9.25 29.64,9.51 29.64,9.63 28.5,10.78 24.56,10.78 24.31,11.03 24.31,11.49 24.3,11.5 24.3,12.23 24.1,12.44 24.1,14.08 23.85,14.33 22.83,14.33 22.58,14.59 22.58,22.23 v1(22.22,22.59)
  L19_GND w0.089: v3(50.34,8.49) 50.22,8.36 v4(50.22,7.98)
  BOTTOM w0.089: v4(50.22,7.98) 50.09,7.86 50.09,7.6 50.33,7.36 JX2.50
IO_L16_13_JX2_P: length 72.5
  TOP w0.089: U1.AE20 v1(22.22,23.59)
  L4_SIG w0.089: v1(22.22,23.59) 22.83,22.97 22.83,14.69 22.94,14.59 23.95,14.59 24.35,14.18 24.35,12.54 24.56,12.34 24.56,11.6 24.56,11.59 24.56,11.14 24.67,11.03 28.61,11.03 29.9,9.74 29.9,9.61 30,9.51 30.91,9.51 31.17,9.25 32.18,9.25 32.44,9 32.44,6.33 32.31,6.2 32.31,5.55 32.42,5.44 32.84,5.44 32.95,5.55 32.95,8.21 33.35,8.62 33.83,8.62 34.34,8.11 34.98,8.11 35.36,7.73 35.36,7.12 34.96,6.71 34.32,6.71 34.22,6.61 34.22,6.31 34.32,6.2 34.96,6.2 35.36,5.8 35.36,4.7 34.7,4.05 33.71,4.05 33.45,3.79 33.45,3.42 33.71,3.16 34.4,3.16 34.61,3.37 35.1,3.37 35.3,3.16 47.91,3.16 48.42,2.65 52.43,2.65 52.76,2.98 52.76,3.31 52.52,3.54 49.78,3.54 49.76,3.52 49.27,3.52 48.93,3.86 48.93,3.96 48.82,4.07 48.82,6.06 49.35,6.59 49.46,6.59 49.96,7.09 49.96,8.24 v3(49.71,8.49)
  L19_GND w0.089: v4(49.71,7.98) v3(49.71,8.49)
  BOTTOM w0.089: JX2.48 49.53,7.29 49.84,7.6 49.84,7.86 v4(49.71,7.98)
IO_L16_33_JX1_N: length 73.1
  TOP w0.089: U1.L2 v1(37.22,42.59)
  L3_SIG w0.089: v1(37.22,42.59) 36.84,42.96 36.84,43.05 36.88,43.09 36.88,43.45 36.88,43.45 36.88,46.7 36.54,47.04 35.98,47.04 35.73,47.29 35.73,47.8 36.05,48.11 36.35,48.11 36.88,48.64 36.88,50.65 36.5,51.04 34.47,51.04 34.22,51.29 34.22,54.82 33.81,55.23 32.8,55.23 32.69,55.33 32.69,55.88 32.8,55.99 34.74,55.99 34.85,55.88 34.85,52.45 35.38,51.92 37.5,51.92 37.77,52.2 37.77,54.97 38.22,55.42 38.6,55.42 39.04,55.86 39.04,58.02 39.8,58.78 46.03,58.78 46.28,59.04 46.28,59.67 46.03,59.93 31.17,59.93 30.91,59.67 30.91,58.78 31.17,58.53 36.76,58.53 37.01,58.27 37.01,57.64 36.88,57.51 36.88,55.61 36.5,55.23 35.99,55.23 35.61,55.61 35.61,56.62 v1(35.87,56.88)
  BOTTOM w0.089: v1(35.87,56.88) 35.61,56.62 35.61,56.5 35.93,56.18 JX1.13
IO_L16_33_JX1_P: length 73.1
  TOP w0.089: U1.M2 v1(36.22,42.59)
  L3_SIG w0.089: v1(36.22,42.59) 36.59,42.96 36.59,43.16 36.63,43.2 36.63,43.34 36.62,43.34 36.62,46.59 36.43,46.78 35.88,46.78 35.48,47.19 35.48,47.9 35.94,48.37 36.24,48.37 36.62,48.75 36.62,50.55 36.39,50.78 34.36,50.78 33.96,51.18 33.96,54.72 33.71,54.97 32.69,54.97 32.44,55.23 32.44,55.99 32.69,56.24 34.85,56.24 35.1,55.99 35.1,52.56 35.49,52.18 37.39,52.18 37.52,52.31 37.52,55.08 38.11,55.67 38.49,55.67 38.79,55.97 38.79,58.13 39.7,59.04 45.92,59.04 46.03,59.14 46.03,59.57 45.92,59.67 31.27,59.67 31.17,59.57 31.17,58.89 31.27,58.78 36.86,58.78 37.26,58.38 37.26,57.53 37.14,57.41 37.14,55.5 36.61,54.97 35.89,54.97 35.36,55.5 35.36,56.62 v1(35.1,56.88)
  BOTTOM w0.089: JX1.11 35.13,56.14 35.4,56.41 35.4,56.59 v1(35.1,56.88)
IO_L16_34_JX4_N: length 72.1
  TOP w0.089: U1.A10 v1(47.22,34.59)
  L18_SIG w0.089: v1(47.22,34.59) 46.84,34.96 46.84,37.8 46.46,38.18 46.29,38.18 46.26,38.21 45.26,38.21 45.22,38.25 45.08,38.25 44.88,38.45 44.88,43.78 44.23,44.43 43.97,44.43 43.61,44.79 43.61,45.85 46.53,48.77 46.53,50.04 47.15,50.65 59.74,50.65 60.55,49.85 60.77,49.85 60.97,49.65 60.97,49.43 62.96,47.44 62.96,47.36 63.31,47.02 63.38,47.02 67.03,43.37 67.03,42.38 67.64,41.76 70.03,41.76 70.79,42.53 71.3,42.53 74.22,39.61 74.22,32.64 75,31.86 76.64,31.86 76.76,31.74 76.76,30.1 77.4,29.47 77.4,28.66 77.4,28.45 77.92,27.92 79.55,27.92 79.68,27.79 79.68,27.54 79.81,27.41 80.06,27.41 v1(80.19,27.54)
  BOTTOM w0.089: v1(80.19,27.54) 80.35,27.71 80.5,27.71 80.84,27.37 JX4.60
IO_L16_34_JX4_P: length 72.1
  TOP w0.089: U1.B10 v1(46.22,34.59)
  L18_SIG w0.089: v1(46.22,34.59) 46.59,34.96 46.59,37.69 46.35,37.92 46.18,37.92 46.15,37.95 45.01,37.95 44.62,38.34 44.62,43.67 44.12,44.18 43.87,44.18 43.36,44.69 43.36,45.96 46.28,48.88 46.28,50.15 47.04,50.91 59.85,50.91 60.65,50.1 60.87,50.1 61.22,49.76 61.22,49.54 63.22,47.54 63.22,47.47 63.41,47.27 63.49,47.27 63.56,47.2 63.56,47.2 67.28,43.48 67.28,42.48 67.74,42.02 69.92,42.02 70.69,42.78 71.4,42.78 74.47,39.71 74.47,32.75 75.11,32.11 76.75,32.11 77.01,31.85 77.01,30.21 77.65,29.57 77.65,28.56 78.03,28.18 v1(80.19,28.18)
  BOTTOM w0.089: JX4.58 80.82,28.17 80.57,27.92 80.44,27.92 v1(80.19,28.18)
IO_L16_35_TX_D3_N: length 32.2
  TOP w0.089: v6(62.8,28.09) U17.E9 ; U1.D16 v1(44.22,27.59)
  L6_SIG w0.089: v1(44.22,27.59) 43.95,27.59 43.87,27.51 43.87,26.46 44.08,26.25 48.95,26.25 49.33,25.87 49.33,25.4 48.8,24.87 48.54,24.87 48.31,24.64 48.31,24.34 48.54,24.11 48.8,24.11 49.33,23.58 49.33,23.56 49.46,23.43 49.46,23.37 49.65,23.18 52.5,23.18 52.88,23.56 52.88,23.6 53.27,23.98 54.15,23.98 54.54,23.6 54.54,23.56 54.92,23.18 55.25,23.18 57.13,23.18 57.43,23.48 57.82,23.48 58.35,22.95 58.35,22.44 58.5,22.29 59.08,22.29 59.23,22.44 59.23,22.95 59.76,23.48 60,23.48 61.52,25 62.87,25 63.13,25.25 63.13,27.16 63.3,27.54 63.3,27.79 63.04,28.05 v6(62.8,28.09)
IO_L16_35_TX_D3_P: length 32.3
  TOP w0.089: U1.E16 v1(43.22,27.59) ; v6(63.6,27.29) U17.D8
  L6_SIG w0.089: v1(43.22,27.59) 43.26,27.59 43.62,27.23 43.62,26.35 43.97,26 48.84,26 49.07,25.77 49.07,25.51 48.69,25.13 48.44,25.13 48.06,24.75 48.06,24.24 48.44,23.86 48.69,23.86 49.07,23.48 49.07,23.45 49.2,23.33 49.2,23.27 49.55,22.92 52.61,22.92 53.14,23.45 53.14,23.5 53.37,23.73 54.05,23.73 54.28,23.5 54.28,23.45 54.81,22.92 55.15,22.92 57.24,22.92 57.54,23.22 57.71,23.22 58.09,22.84 58.09,22.33 58.39,22.03 59.19,22.03 59.49,22.33 59.49,22.84 59.87,23.22 60.1,23.22 61.63,24.75 63.17,24.75 63.93,25.51 63.93,26.96 v6(63.6,27.29)
IO_L17_12_JX2_N: length 73
  TOP w0.089: U1.AE15 v1(22.22,28.59)
  L6_SIG w0.089: v1(22.22,28.59) 22.59,28.22 23.49,28.22 23.81,27.9 23.81,26.37 24,26.18 24.46,26.18 24.81,25.83 24.81,25.5 25.12,25.18 28.46,25.18 28.81,24.83 28.81,24.52 29.15,24.18 29.46,24.18 29.81,23.83 29.81,23.52 30.15,23.18 30.46,23.18 30.81,22.83 30.81,22.52 31.15,22.18 31.46,22.18 31.88,21.76 31.88,21.45 32.08,21.25 32.35,21.25 32.43,21.18 32.46,21.18 32.81,20.83 32.81,20.8 32.88,20.73 32.88,20.45 33.08,20.25 33.35,20.25 33.43,20.18 33.46,20.18 34.88,18.76 34.88,18.45 35.08,18.25 35.38,18.25 35.45,18.18 35.46,18.18 35.81,17.83 35.81,17.82 35.88,17.75 35.88,17.45 36.08,17.25 45.35,17.25 45.36,17.25 45.9,17.25 47.3,15.86 50.34,15.86 50.47,15.98 50.73,15.98 50.86,16.11 54.89,16.11 55.15,15.86 57.11,15.86 57.84,15.13 57.84,13.97 57.94,13.87 58.55,13.87 58.98,13.44 58.98,13.21 59.38,12.81 59.52,12.81 59.89,12.44 59.89,12.26 60.36,11.79 60.36,11.53 60.61,11.28 66.89,11.28 66.99,11.18 69.75,11.18 70.28,10.65 70.28,8.77 69.75,8.24 67.62,8.24 67.24,8.62 67.24,9.51 66.98,9.76 65.04,9.76 64.96,9.84 64.68,9.84 64.6,9.76 64.06,9.76 63.68,9.38 63.68,8.31 63.81,8.19 v1(63.81,7.86)
  BOTTOM w0.089: v1(63.81,7.86) 63.66,7.71 63.66,7.58 63.93,7.32 JX2.84
IO_L17_12_JX2_P: length 73
  TOP w0.089: U1.AE16 v1(22.22,27.59)
  L6_SIG w0.089: v1(63.3,7.86) 63.3,8.19 63.43,8.31 63.43,9.48 63.95,10.01 64.49,10.01 64.58,10.1 65.07,10.1 65.15,10.01 67.09,10.01 67.49,9.61 67.49,8.72 67.72,8.49 69.65,8.49 70.03,8.87 70.03,10.55 69.65,10.93 66.88,10.93 66.78,11.03 60.51,11.03 60.11,11.43 60.11,11.68 59.63,12.16 59.63,12.33 59.41,12.55 59.28,12.55 58.73,13.11 58.73,13.34 58.45,13.62 57.84,13.62 57.58,13.87 57.58,15.02 57,15.6 55.04,15.6 54.79,15.86 50.97,15.86 50.84,15.72 50.57,15.72 50.45,15.6 47.19,15.6 45.79,17 45.46,17 45.46,17 35.97,17 35.62,17.34 35.62,17.64 35.55,17.72 35.55,17.73 35.35,17.93 35.34,17.93 35.27,18 34.97,18 34.62,18.34 34.62,18.62 33.55,19.7 33.55,19.73 33.35,19.93 33.32,19.93 33.25,20 32.97,20 32.62,20.34 32.62,20.62 32.55,20.7 32.55,20.73 32.35,20.93 32.32,20.93 32.25,21 31.97,21 31.62,21.34 31.62,21.66 31.35,21.93 31.04,21.93 30.55,22.42 30.55,22.73 30.35,22.93 30.04,22.93 29.55,23.42 29.55,23.73 29.35,23.93 29.04,23.93 28.55,24.42 28.55,24.73 28.35,24.93 25.02,24.93 24.54,25.41 24.54,25.43 24.55,25.45 24.55,25.73 24.35,25.93 23.89,25.93 23.55,26.27 23.55,27.79 23.38,27.96 22.48,27.96 22.34,28.11 22.28,28.11 22.22,28.05 v1(22.22,27.59)
  BOTTOM w0.089: v1(63.3,7.86) 63.43,7.73 63.43,7.6 63.13,7.3 JX2.82
IO_L17_13_JX2_N: length 72.8
  TOP w0.089: U1.AD19 v1(23.22,24.59)
  L6_SIG w0.089: v3(52.63,12.94) 52.63,11.92 52.88,11.67 53.39,11.67 53.77,11.28 53.77,8.74 53.39,8.36 53.39,7.58 53.62,7.35 55.6,7.35 55.93,7.01 55.93,6.54 55.6,6.2 47.67,6.2 47.3,6.58 47.3,7.1 47.67,7.47 50.47,7.47 50.85,7.86 50.85,13.19 50.6,13.44 49.58,13.44 49.2,13.06 49.2,11.16 48.82,10.78 32.95,10.78 30.41,13.32 30.15,13.32 29.9,13.06 29.16,13.06 28.01,14.21 26.16,14.21 25.78,14.59 25.78,14.84 25.4,15.22 24.56,15.22 23.62,16.16 23.62,24.82 23.43,25.01 23.31,25.01 23.17,24.87 23.17,24.64 v1(23.22,24.59)
  L19_GND w0.089: v4(52.63,12.43) v3(52.63,12.94)
  BOTTOM w0.089: v4(52.63,12.43) 52.47,12.26 52.47,12.05 52.73,11.78 JX2.55
IO_L17_13_JX2_P: length 72.8
  TOP w0.089: U1.AD18 v1(23.22,25.59)
  L6_SIG w0.089: v1(23.22,25.59) 23.22,25.41 23.36,25.27 23.51,25.27 23.52,25.28 23.88,24.93 23.88,16.27 24.67,15.48 25.5,15.48 26.03,14.95 26.03,14.69 26.27,14.46 28.12,14.46 29.26,13.32 29.79,13.32 30.05,13.57 30.51,13.57 33.05,11.03 48.71,11.03 48.95,11.26 48.95,13.17 49.48,13.7 50.7,13.7 51.11,13.29 51.11,7.75 50.58,7.22 47.77,7.22 47.55,7 47.55,6.68 47.77,6.46 55.49,6.46 55.68,6.64 55.68,6.91 55.49,7.09 53.52,7.09 53.14,7.47 53.14,8.47 53.52,8.85 53.52,11.18 53.29,11.41 52.78,11.41 52.38,11.81 52.38,11.92 52.25,12.05 52.12,12.05 52,12.17 52,12.3 v4(52.12,12.43) 52.25,12.43 52.38,12.55 52.38,12.68 v3(52.12,12.94)
  L19_GND w0.089: v4(52.12,12.43) v3(52.12,12.94)
  BOTTOM w0.089: v4(52.12,12.43) 52.25,12.3 52.25,12.05 51.93,11.72 JX2.53
IO_L17_33_JX1_N: length 73.8
  TOP w0.089: U1.M4 v1(36.22,40.59)
  L15_SIG w0.089: v1(35.99,49.64) 35.74,49.38 35.7,49.38 35.61,49.3 35.61,48.26 35.21,47.86 34.62,47.86 33.71,48.77 33.71,50.38 34.47,51.14 34.47,54.19 35,54.72 47.83,54.72 48.06,54.95 48.06,55.63 47.57,56.12 33.78,56.12 33.77,56.11 33.28,56.11 33.27,56.12 33.18,56.12 32.82,55.76 32.82,52.16 33.33,51.65 33.33,49.28 32.69,48.64 32.69,47.71 33.18,47.23 35.46,47.23 36.25,46.44 36.25,45.72 34.85,44.33 34.85,43.56 34.57,43.29 34.07,43.29 33.81,43.03 33.81,36.41 34.04,36.18 34.36,36.18 34.6,36.41 34.6,40.98 34.87,41.25 35.6,41.25 35.87,40.98 35.87,40.84 35.96,40.75 36.06,40.75 v1(36.22,40.59)
  BOTTOM w0.089: JX1.14 35.93,50.21 35.74,50.02 35.74,49.89 v1(35.99,49.64)
IO_L17_33_JX1_P: length 73.8
  TOP w0.089: U1.N4 v1(35.22,40.59)
  L15_SIG w0.089: v1(35.22,40.59) 35.25,40.62 35.49,40.62 35.61,40.75 35.61,40.88 35.49,41 34.97,41 34.85,40.88 34.85,36.3 34.47,35.92 33.93,35.92 33.55,36.3 33.55,43.13 33.96,43.54 34.47,43.54 34.6,43.67 34.6,44.43 35.99,45.83 35.99,46.34 35.36,46.97 33.07,46.97 32.44,47.61 32.44,48.75 33.07,49.38 33.07,51.54 32.56,52.05 32.56,55.86 33.07,56.37 33.38,56.37 33.39,56.36 33.67,56.36 33.68,56.37 47.68,56.37 48.31,55.73 48.31,54.85 47.93,54.46 35.1,54.46 34.72,54.08 34.72,51.04 33.96,50.27 33.96,48.88 34.72,48.11 35.1,48.11 35.36,48.37 35.36,49.51 v1(35.23,49.64)
  BOTTOM w0.089: JX1.12 35.13,50.38 35.49,50.02 35.49,49.89 v1(35.23,49.64)
IO_L17_34_JX4_N: length 72.3
  TOP w0.089: U1.A8 v1(47.22,36.59)
  L6_SIG w0.089: v1(84.51,23.48) 84.51,23.6 84.76,23.86 84.89,23.86 85.02,23.73 85.02,23.48 85.08,23.41 85.21,23.41 85.27,23.48 85.27,23.73 85.4,23.86 85.55,23.86 86.03,23.38 86.03,23.06 85.81,22.84 84.27,22.84 82.79,21.35 82.79,20.79 83.19,20.38 87.94,20.38 88.32,20 88.32,19.29 87.94,18.9 77.78,18.9 73.84,22.84 73.84,33.38 73.33,33.89 70.85,33.89 70.29,34.45 70.21,34.45 68.36,36.3 64.41,36.3 64.33,36.22 64.05,36.22 63.97,36.3 59.76,36.3 59.13,35.67 57.73,35.67 57.27,35.2 55.15,35.2 55.1,35.16 54.35,35.16 53.75,35.76 51.89,35.76 51.65,36.01 50.35,36.01 50.16,35.82 48.84,35.82 48.44,36.22 47.59,36.22 v1(47.22,36.59)
  BOTTOM w0.089: JX4.69 85.12,23.37 84.82,23.67 84.7,23.67 v1(84.51,23.48)
IO_L17_34_JX4_P: length 72.3
  TOP w0.089: U1.A9 v1(47.22,35.59)
  L6_SIG w0.089: v1(84.51,24.11) 85.66,24.11 86.29,23.49 86.29,22.96 85.91,22.59 84.38,22.59 83.04,21.25 83.04,20.89 83.29,20.64 88.04,20.64 88.57,20.11 88.57,19.18 88.04,18.65 77.67,18.65 73.59,22.74 73.59,33.28 73.23,33.64 70.74,33.64 70.19,34.19 70.11,34.19 68.25,36.05 64.51,36.05 64.43,35.97 63.94,35.97 63.86,36.05 59.87,36.05 59.23,35.41 57.84,35.41 57.37,34.95 55.25,34.95 55.21,34.91 54.24,34.91 53.65,35.5 51.78,35.5 51.53,35.75 50.45,35.75 50.21,35.5 48.79,35.5 48.33,35.96 47.59,35.96 v1(47.22,35.59)
  BOTTOM w0.089: v1(84.51,24.11) 84.72,23.9 84.84,23.9 85.11,24.17 JX4.67
IO_L17_35_TX_D4_N: length 32.8
  TOP w0.089: v6(63.6,28.09) U17.E8 ; U1.B15 v1(46.22,28.59)
  L15_SIG w0.089: v1(46.22,28.59) 46.06,28.59 45.77,28.3 45.77,28.17 46.01,27.92 46.19,27.92 46.48,28.22 47.51,28.22 47.93,28.64 47.93,29.04 48.21,29.32 49.18,29.32 49.46,29.04 49.46,28.03 50.24,27.24 52.02,27.24 52.88,26.38 52.88,23.98 52.88,23.98 52.88,23.86 53.14,23.6 54.83,23.6 55.25,23.18 55.53,23.18 55.79,23.43 57.09,23.43 57.21,23.56 57.21,24.06 57.33,24.17 57.33,25.16 57.81,25.64 58.48,25.64 58.96,25.16 58.96,23.56 59.09,23.43 60.1,23.43 61.67,25 62.54,25 62.67,25.12 62.67,25.4 62.5,25.57 62.5,26.49 62.5,26.62 62.67,26.79 62.72,26.79 63.1,27.17 63.1,27.21 63.42,27.54 63.42,27.54 63.47,27.59 63.72,27.59 63.92,27.79 63.92,27.91 63.74,28.09 v6(63.6,28.09)
IO_L17_35_TX_D4_P: length 31.6
  TOP w0.089: U1.B16 v1(46.22,27.59) ; v6(64.4,27.29) U17.D7
  L15_SIG w0.089: v6(64.4,27.29) 64.31,27.38 64.31,27.54 64.23,27.62 64.11,27.62 63.9,27.41 63.9,27.29 63.9,27.29 63.9,27.17 63.55,26.82 63.5,26.82 63.3,26.62 63.3,26.14 63.1,25.94 63.1,25.57 62.92,25.39 62.92,25.02 62.65,24.75 61.77,24.75 60.21,23.18 58.98,23.18 58.7,23.45 58.7,25.05 58.38,25.38 57.91,25.38 57.58,25.05 57.58,24.07 57.47,23.96 57.47,23.45 57.19,23.18 55.89,23.18 55.64,22.92 55.15,22.92 54.72,23.35 53.03,23.35 52.63,23.75 52.63,24.09 52.63,26.27 51.91,26.99 50.14,26.99 49.2,27.92 49.2,28.94 49.07,29.06 48.31,29.06 48.19,28.94 48.19,28.53 47.62,27.96 46.59,27.96 46.3,27.67 v1(46.22,27.59)
IO_L18_12_JX2_N: length 72.9
  TOP w0.089: U1.AF17 v1(21.22,26.59)
  L14_SIG w0.089: v3(63.81,12.81) 63.81,13.04 63.73,13.12 63.73,13.52 63.38,13.87 63.38,16.24 63.76,16.62 64.7,16.62 65.08,17 65.08,18.25 64.55,18.78 63.57,18.78 63.07,18.27 62.64,18.27 62.13,18.78 60.65,18.78 60.25,18.37 60.25,16.75 60.65,16.35 62.32,16.35 62.43,16.24 62.43,14.33 62.18,14.08 61.38,14.08 61.16,13.86 59.22,13.86 59.19,13.82 49.31,13.82 45.88,17.25 27.97,17.25 27.81,17.42 27.81,17.83 27.46,18.18 27.05,18.18 26.81,18.42 26.81,24.83 26.46,25.18 26.15,25.18 25.81,25.52 25.81,25.83 25.46,26.18 25.14,26.18 24.81,26.51 24.81,26.83 24.46,27.18 21.53,27.18 21.26,26.91 21.26,26.63 v1(21.22,26.59)
  L19_GND w0.089: v4(63.81,12.43) v3(63.81,12.81)
  BOTTOM w0.089: JX2.83 63.93,11.67 63.68,11.92 63.68,12.3 v4(63.81,12.43)
IO_L18_12_JX2_P: length 72.9
  TOP w0.089: U1.AE17 v1(22.22,26.59)
  L14_SIG w0.089: v1(22.22,26.59) 22.02,26.4 21.77,26.4 21.57,26.6 21.57,26.85 21.64,26.93 24.35,26.93 24.55,26.73 24.55,26.41 25.04,25.93 25.35,25.93 25.55,25.73 25.55,25.41 26.04,24.93 26.35,24.93 26.55,24.73 26.55,18.31 26.94,17.93 27.35,17.93 27.55,17.73 27.55,17.31 27.87,17 45.77,17 49.2,13.57 59.29,13.57 59.32,13.6 61.27,13.6 61.49,13.82 62.28,13.82 62.68,14.23 62.68,16.34 62.43,16.6 60.76,16.6 60.5,16.85 60.5,18.27 60.76,18.52 62.03,18.52 62.54,18.02 63.17,18.02 63.68,18.52 64.44,18.52 64.82,18.14 64.82,17.1 64.59,16.87 63.66,16.87 63.13,16.34 63.13,13.76 63.47,13.42 63.47,13.04 63.3,12.86 v3(63.3,12.81)
  L19_GND w0.089: v4(63.3,12.43) v3(63.3,12.81)
  BOTTOM w0.089: v4(63.3,12.43) 63.46,12.26 63.46,12.02 63.13,11.69 JX2.81
IO_L18_13_JX2_N: length 72.1
  TOP w0.089: U1.AF18 v1(21.22,25.59)
  L4_SIG w0.089: v1(21.22,25.59) 21.59,25.22 21.59,14.48 21.72,14.34 21.72,12.96 22.13,12.55 23.19,12.55 23.29,12.45 23.29,10.14 23.8,9.63 25.22,9.63 25.83,9.02 25.83,5.82 26.34,5.32 27.89,5.32 28.12,5.08 28.12,3.66 28.37,3.41 30.91,3.41 31.29,3.79 31.29,4.17 31.55,4.43 31.8,4.43 32.18,4.05 32.18,2.01 32.56,1.63 56.57,1.63 56.95,2.01 56.95,4.97 56.35,5.57 53.27,5.57 52.76,6.08 v3(52.76,8.49)
  L19_GND w0.089: v3(52.76,8.49) 52.63,8.36 v4(52.63,7.98)
  BOTTOM w0.089: v4(52.63,7.98) 52.5,7.86 52.5,7.6 52.73,7.38 JX2.56
IO_L18_13_JX2_P: length 72.1
  TOP w0.089: U1.AE18 v1(22.22,25.59)
  L4_SIG w0.089: v1(22.22,25.59) 21.84,25.22 21.84,14.59 21.98,14.45 21.98,13.06 22.23,12.81 23.29,12.81 23.55,12.55 23.55,10.25 23.91,9.89 25.33,9.89 26.09,9.13 26.09,5.93 26.45,5.57 27.99,5.57 28.37,5.19 28.37,3.77 28.48,3.66 30.81,3.66 31.04,3.9 31.04,4.28 31.44,4.68 31.91,4.68 32.44,4.15 32.44,2.12 32.67,1.89 56.46,1.89 56.69,2.12 56.69,4.86 56.24,5.32 53.16,5.32 52.5,5.97 52.5,7.09 52.38,7.22 52.17,7.22 52,7.4 52,7.6 52.12,7.73 52.38,7.73 52.5,7.86 52.5,8.24 52.25,8.49 v3(52.12,8.49)
  L19_GND w0.089: v4(52.12,7.98) v3(52.12,8.49)
  BOTTOM w0.089: v4(52.12,7.98) 52.25,7.86 52.25,7.6 51.93,7.28 JX2.54
IO_L18_33_JX1_N: length 73.2
  TOP w0.089: U1.M1 v1(36.22,43.59)
  L18_SIG w0.089: v1(38.28,56.88) 38.03,56.62 38.03,54.21 37.77,53.96 37.14,53.96 36.88,54.21 36.88,58.55 36.78,58.66 36.48,58.66 36.37,58.55 36.37,57.2 36.46,57.12 36.46,56.63 36.37,56.55 36.37,56.24 35.49,55.35 35.49,54.59 35.1,54.21 34.34,54.21 33.96,54.59 33.96,55.35 33.58,55.73 33.3,55.73 32.92,55.35 30.68,55.35 30.15,55.88 30.15,59.31 29.92,59.54 29.02,59.54 28.94,59.46 28.45,59.46 28.36,59.54 28.01,59.54 27.51,60.05 23.75,60.05 23.37,59.67 22.45,59.67 22.2,59.42 22.2,58.66 22.45,58.4 28.61,58.4 29.14,57.87 29.14,55.59 28.75,55.2 28.75,54.99 28.9,54.85 32.42,54.85 32.82,54.44 32.82,53.85 32.42,53.45 30.64,53.45 30.41,53.22 30.41,52.66 30.47,52.6 32.97,52.6 33.33,52.24 33.33,51.69 33.05,51.42 31.78,51.42 31.68,51.31 31.68,51.01 31.91,50.78 32.92,50.78 33.33,50.38 33.33,49.31 32.97,48.96 32.88,48.96 32.54,48.62 31.78,48.62 31.55,48.39 31.55,48.22 32.03,47.73 33.05,47.73 33.45,47.33 33.45,45.27 34.03,44.69 34.37,44.69 34.46,44.6 34.74,44.6 34.82,44.69 35.59,44.69 35.87,44.41 35.87,43.94 v1(36.22,43.59)
  BOTTOM w0.089: JX1.19 38.33,56.19 38.03,56.5 38.03,56.62 v1(38.28,56.88)
IO_L18_33_JX1_P: length 73.2
  TOP w0.089: U1.N1 v1(35.22,43.59)
  L18_SIG w0.089: v1(37.52,56.88) 37.77,56.62 37.77,54.32 37.67,54.21 37.24,54.21 37.14,54.32 37.14,58.66 36.88,58.91 36.37,58.91 36.12,58.66 36.12,57.1 36.2,57.02 36.2,56.74 36.12,56.66 36.12,56.35 35.23,55.46 35.23,54.7 35,54.46 34.45,54.46 34.22,54.7 34.22,55.46 33.69,55.99 33.2,55.99 32.82,55.61 30.79,55.61 30.41,55.99 30.41,59.42 30.02,59.8 28.91,59.8 28.83,59.72 28.55,59.72 28.47,59.8 28.12,59.8 27.61,60.31 23.64,60.31 23.26,59.93 22.34,59.93 21.94,59.52 21.94,58.55 22.34,58.15 28.5,58.15 28.88,57.77 28.88,55.69 28.5,55.31 28.5,54.89 28.8,54.59 32.31,54.59 32.56,54.34 32.56,53.96 32.31,53.7 30.53,53.7 30.15,53.32 30.15,52.56 30.36,52.35 32.86,52.35 33.07,52.14 33.07,51.8 32.95,51.67 31.68,51.67 31.42,51.42 31.42,50.91 31.8,50.53 32.82,50.53 33.07,50.27 33.07,49.42 32.87,49.21 32.77,49.21 32.44,48.88 31.68,48.88 31.29,48.5 31.29,48.11 31.93,47.48 32.95,47.48 33.2,47.23 33.2,45.16 33.93,44.43 34.27,44.43 34.35,44.35 34.84,44.35 34.92,44.43 35.49,44.43 35.61,44.3 35.61,43.99 v1(35.22,43.59)
  BOTTOM w0.089: v1(37.52,56.88) 37.81,56.59 37.81,56.41 37.53,56.13 JX1.17
